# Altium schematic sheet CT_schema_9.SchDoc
size 391 x 238 mm
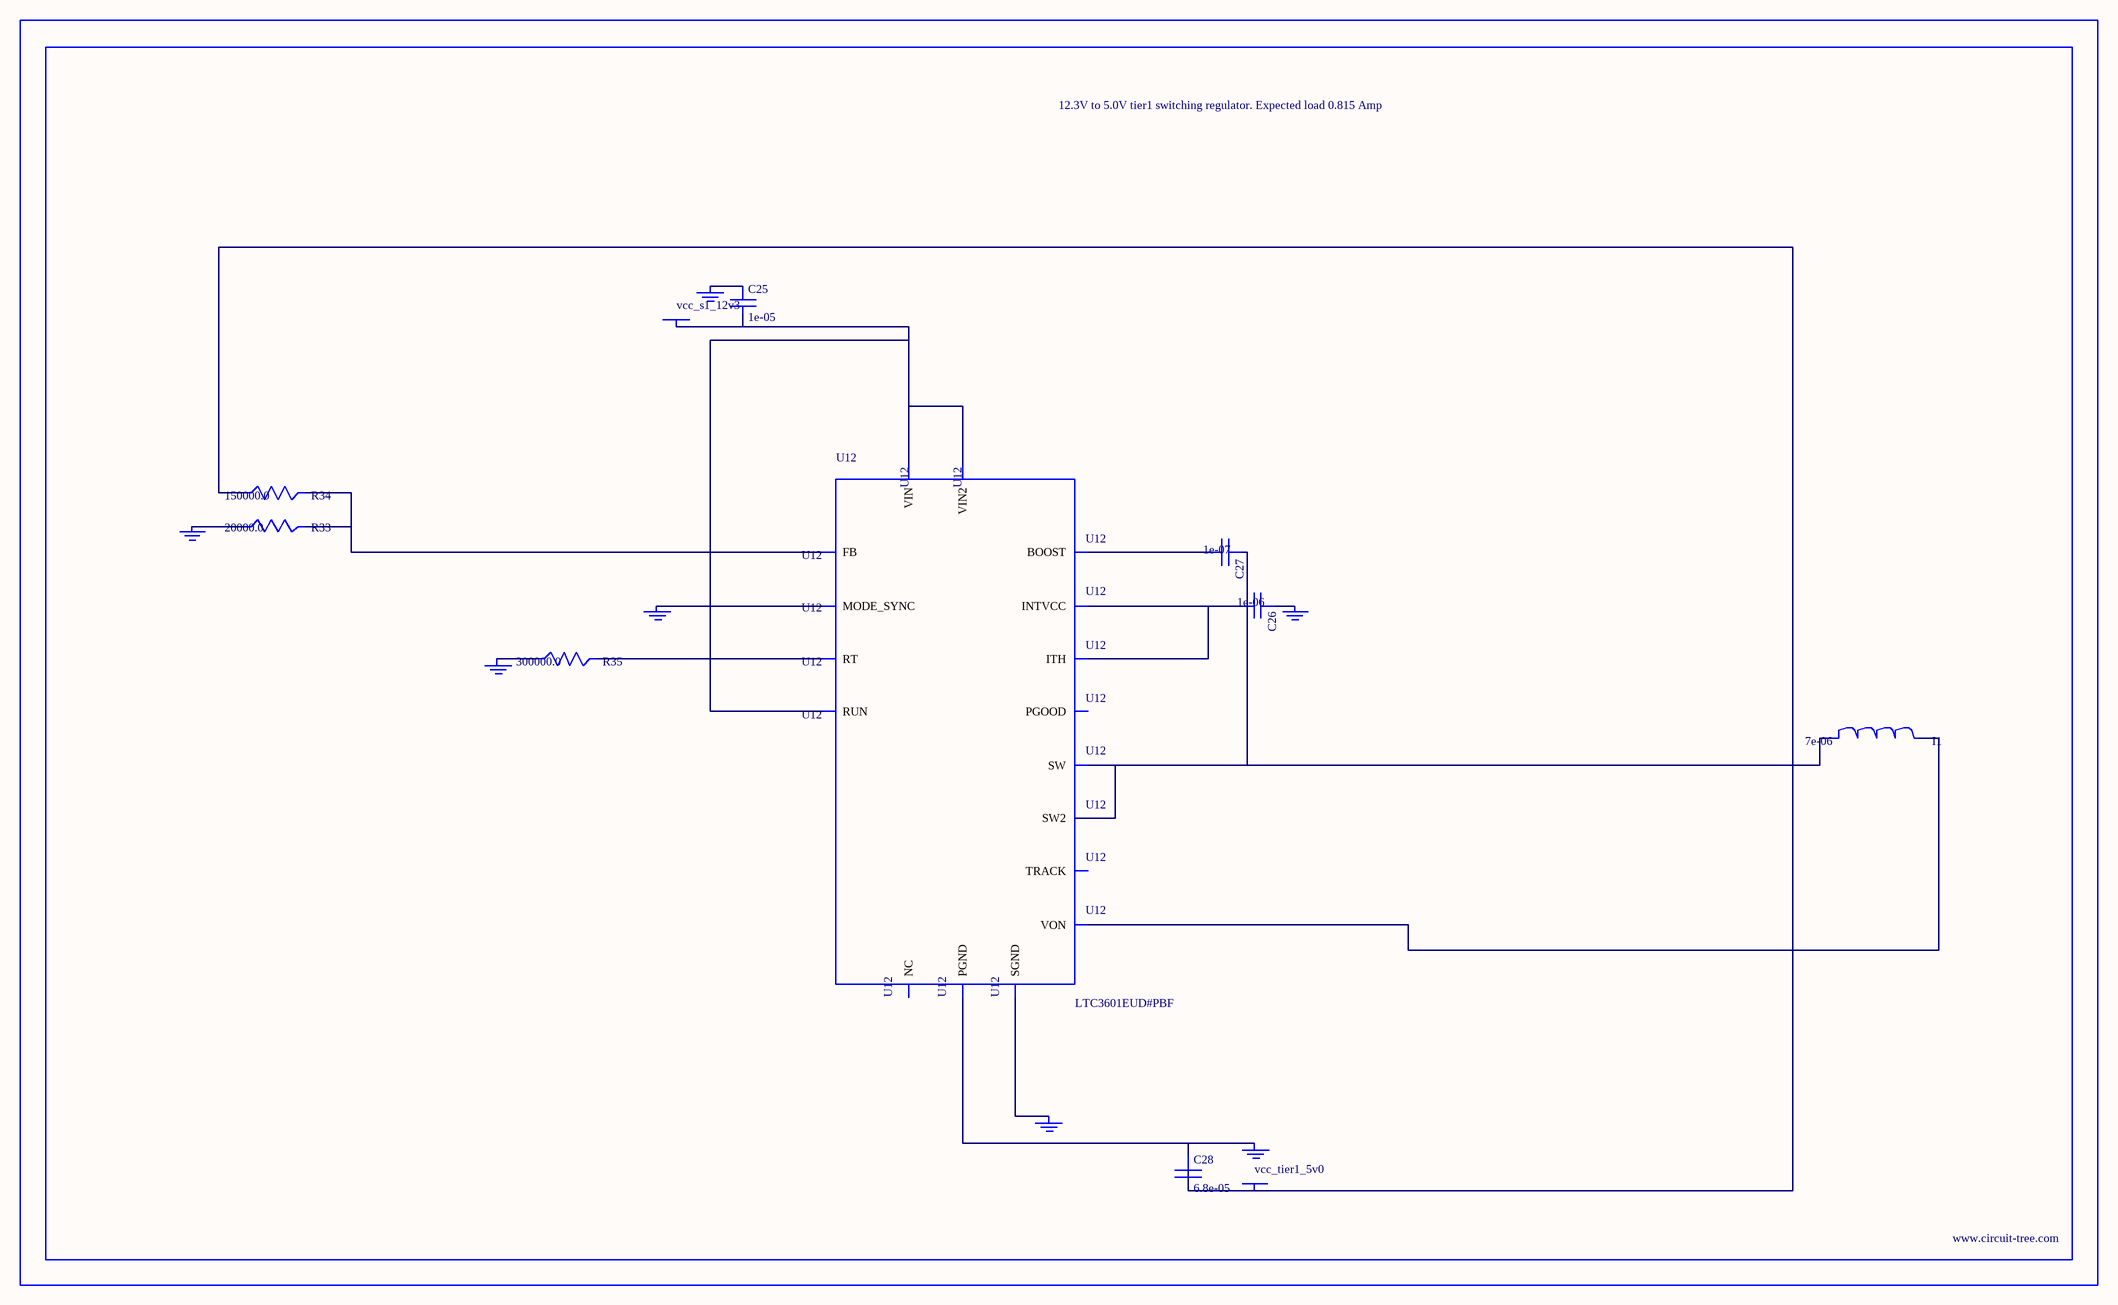
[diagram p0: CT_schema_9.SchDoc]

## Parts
BORDER8  (no value)
C25  1e-05  [C0805]
C26  1e-06  [C0603]
C27  1e-07  [C0402]
C28  6.8e-05  [2220]
GND_INSTANCE_8_0  (no value)
GND_INSTANCE_8_1  (no value)
GND_INSTANCE_8_2  (no value)
GND_INSTANCE_8_3  (no value)
GND_INSTANCE_8_4  (no value)
GND_INSTANCE_8_5  (no value)
GND_INSTANCE_8_6  (no value)
I1  7e-06  [DR1040]
POWER_INSTANCE_8_0  vcc_s1_12v3
POWER_INSTANCE_8_1  vcc_tier1_5v0
R33  20000.0  [R0603]
R34  150000.0  [R0603]
R35  300000.0  [R0603]
U12  LTC3601EUD#PBF  [QFN-16_EP]

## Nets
NetC25_1: C25.1 GND_INSTANCE_8_5.0(GND)
NetC25_2: C25.2 POWER_INSTANCE_8_0.0(PWR) U12.14(RUN) U12.15(VIN) U12.16(VIN2)
NetC26_1: C26.1 GND_INSTANCE_8_1.0(GND)
NetC26_2: C26.2 U12.7(INTVCC) U12.12(ITH)
NetC27_1: C27.1 I1.1 U12.3(SW) U12.4(SW2)
NetC27_2: C27.2 U12.6(BOOST)
NetC28_1: C28.1 GND_INSTANCE_8_6.0(GND) U12.17(PGND)
NetC28_2: C28.2 I1.2 POWER_INSTANCE_8_1.0(PWR) R34.1 U12.8(VON)
NetGND_INSTANCE_8_0_0: GND_INSTANCE_8_0.0(GND) U12.1(MODE_SYNC)
NetGND_INSTANCE_8_2_0: GND_INSTANCE_8_2.0(GND) U12.9(SGND)
NetGND_INSTANCE_8_3_0: GND_INSTANCE_8_3.0(GND) R35.1
NetGND_INSTANCE_8_4_0: GND_INSTANCE_8_4.0(GND) R33.1
NetR33_2: R33.2 R34.2 U12.11(FB)
NetR35_2: R35.2 U12.10(RT)

Not connected (* = marked no-connect by the designer): U12 2(PGOOD) 5(NC) 13(TRACK)

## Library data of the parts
BORDER8 = BORDER_PAGE8
C25 = C0805C106K8RACTU
C26 = C0603C105K3RACTU
C27 = C0402C104K3RACTU
C28 = C5750X5R1A686M
GND_INSTANCE_8_0-GND_INSTANCE_8_6 = GND
I1 = DR1040-7R0-R
POWER_INSTANCE_8_0 POWER_INSTANCE_8_1 = PWR
R33 = RC0603JR-0720KL
R34 = RC0603JR-07150KL
R35 = RC0603JR-07300KL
